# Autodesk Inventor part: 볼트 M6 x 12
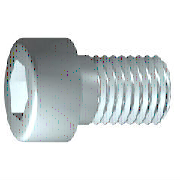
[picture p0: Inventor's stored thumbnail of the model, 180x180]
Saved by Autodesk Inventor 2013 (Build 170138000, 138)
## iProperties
IsCustomPart: 1
Created: 2012-02
Part Number: 볼트 M6 x 12
Material: 강철, 연강
Description: 원통형 머리 캡 나사
Document SubType Name: Modeling
Standard: JIS B 1176
Designer: mdu-01
Standards Organization: JIS
Language: ko-KR
Size Designation: M6 x 12
Categories: <MemberInstance><Categories><Category DisplayName="조임쇠" InternalName="e4da775c-781d-43d5-af7c-5136215cf5a6" Mnemonic="FSTN"><Category DisplayName="볼트" InternalN
Density: 1 g/cm^3
Author: mdu-01
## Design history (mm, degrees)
sketch "스케치1"
  geometry: L1 (-1.333, 0)-(12, 0); L2 (12, 0)-(12, 3); L3 (12, 3)-(2.5, 3); L4 (2.5, 3)-(1.886, 3); L5 (1.886, 3)-(0, 3); L6 (0, 3)-(0, 5); L7 (0, 5)-(-6, 5); L8 (-6, 5)-(-6, 2.887); L9 (-6, 2.887)-(-3, 2.887); L10 (-3, 2.887)-(-1.333, 0); L11 (-9.6, 0)-(15.6, 0) reference; L12 (0, -1)-(0, 6) reference; L13 (2.5, 3)-(0, 3)
  constraints: 22 end point, 6 parallel, 2 collinear, 2 perpendicular, 1 horizontal, 1 point on line
  dimensions: "d1" = 9.5 distance from line of L3.end L2 (= GEL); "d2" = 0.61355 distance of L4.end L3.end (computed from GAL); "d3" = 6 distance between parallel lines of L8 L6 (= KOH); "d4" = 3 distance of L8.end L9.end (= INTI); "d5" = 60 deg angle of L10 L1; "d6" = 6 diameter of L3 L1 (= GD); "d7" = 6 diameter of L5 L1 (= BDM); "d8" = 5.7735 diameter of L9 L1 (= 1.1547 x SW); "d9" = 10 diameter of L7 L1 (= KOD); "d26" = 12 distance between parallel lines of L12 L2 (= NLG)
revolve "본체" sketch "스케치1" stored, may be unused: angle "d10" = 90 deg
sketch "스케치2"
  geometry: L1 (0, -7)-(0, 7) reference; L2 (-7, 0)-(7, 0) reference; L3 (2.887, 0)-(1.443, -2.5); L4 (1.443, -2.5)-(-1.443, -2.5); L5 (-1.443, -2.5)-(-2.887, 0); L6 (-2.887, 0)-(-1.443, 2.5); L7 (-1.443, 2.5)-(1.443, 2.5); L8 (1.443, 2.5)-(2.887, 0); 2 further points
  constraints: 12 end point, 1 coincident, 1 horizontal alignment, 1 point on line, 12 other
extrude "슬롯" join sketch "스케치2" stored distance "d11" = 10; taper "d12" = 0 deg
workplane "Work Plane1"
fillet "Fillet2" dims "d30" = 0.1 (= R)
body "Solid1"
fillet "모깎기1" dims "d17" = 0.6 (= RR)
feature "스레드" dims "d13" = 9.5 (= GEL), "d14" = 0
chamfer "모따기1" distance "d15" = 0.61345 (= -0.5 x SPD + 0.5 x GD); stored, may be unused: second distance "d16" = 0.61345 (= GUL), angle "d27" = 45 deg
other parameters: "GD" = 6 (= NND) [user parameter; used in 2 equation terms], "NLG" = 12 [user parameter; used in 1 equation term], "GEL" = 9.5 [user parameter; used in 2 equation terms], "KOD" = 10 [user parameter; used in 1 equation term], "KOH" = 6 [user parameter; used in 1 equation term], "INTI" = 3 [user parameter; used in 1 equation term], "GAL" = 0.61345 (= 0.61345 x PTC) [user parameter; used in 1 equation term], "GUL" = 0.61345 (= 0.61345 x PTC) [user parameter; used in 1 equation term], "BDM" = 6 (= NND) [user parameter; used in 1 equation term], "SW" = 5 [user parameter; used in 2 equation terms], "RR" = 0.6 [user parameter; used in 1 equation term], "SPD" = 4.7731 (= NND - 1.2269 x PTC) [user parameter; used in 1 equation term], "d19" = 0, "d28" = 0, "d29" = 0, "R" = 0.1 [user parameter; used in 1 equation term], "PHH" = 0.25 [user parameter], "GD1" = 4.7731 (= THREADDIA - 1.2269 x PTC) [user parameter], "THREADDIA" = 6 [user parameter; used in 1 equation term], "FAWI" = 45 deg [user parameter], "PTC" = 1 [user parameter; used in 5 equation terms], "NND" = 6 [user parameter; used in 3 equation terms], "TOA" = 30 deg [user parameter], "E0" = 5.775 (= 1.155 x SW) [user parameter]
